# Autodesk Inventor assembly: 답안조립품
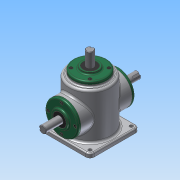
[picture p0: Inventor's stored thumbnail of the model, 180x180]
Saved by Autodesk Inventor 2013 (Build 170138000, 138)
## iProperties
Created: 2015-10
Part Number: 답안조립품
Document SubType Name: Assembly
Designer: Administrator
Author: Administrator
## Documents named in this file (14)
- C:\Users\Administrator\Desktop\451008V1014\답안조립품.iam
- C:\Users\Administrator\Desktop\451008V1014\본체.ipt
- C:\Users\Administrator\Desktop\451008V1014\서브 축.ipt
- 서브 축.ipt
- C:\Users\Administrator\Desktop\451008V1014\커버.ipt
- C:\Users\Administrator\Desktop\451008V1014\오일실.ipt
- C:\Users\Administrator\Desktop\451008V1014\베어링 6203.ipt
- C:\Users\Administrator\Desktop\451008V1014\키 4x4.ipt
- C:\Users\Administrator\Desktop\451008V1014\서브 베벨기어.ipt
- C:\Users\Administrator\Desktop\451008V1014\M4.ipt
- C:\Users\Administrator\Desktop\451008V1014\메인 축.ipt
- 메인 축.ipt
- C:\Users\Administrator\Desktop\451008V1014\키 5x5.ipt
- C:\Users\Administrator\Desktop\451008V1014\메인 베벨기어.ipt
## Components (12 placed, 1 different names)
1. M4:2
2. M4:7
3. M4:8
4. M4:9
5. M4:10
6. M4:12
7. M4:13
8. M4:14
9. M4:11
10. M4:15
11. M4:16
12. M4:17
